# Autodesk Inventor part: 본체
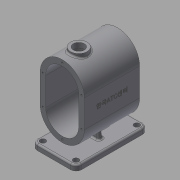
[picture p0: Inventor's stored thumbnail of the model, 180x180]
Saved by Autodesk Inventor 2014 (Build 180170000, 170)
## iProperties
Created: 2016-12
Part Number: 본체
Material: 일반
Document SubType Name: Modeling
Designer: mduedu
Density: 1 g/cm^3
Appearance: Default
Author: mduedu
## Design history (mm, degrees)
sketch "스케치1"
  geometry: L1 (40, -25)-(40, 25); L2 (-40, 25)-(-40, -25); L3 (-40, -25)-(40, 25); L4 (40, -25)-(-40, 25); L5 (0, 25)-(0, -25); A1 r 40 centre (0, 25) between (40, 25) and (-40, 25); A2 r 40 centre (0, -25) between (-40, -25) and (40, -25); 1 further point
  constraints: 10 end point, 4 point on circle, 3 tangent, 2 centre point, 2 midpoint, 2 parallel, 1 vertical
  dimensions: "d0" = 130 dimension on A2 A1; "d2" = 80 distance between parallel lines of L1 L2
extrude "돌출1" new body sketch "스케치1" stored distance "d3" = 100; taper "d4" = 0 deg
feature "쉘1" dims "d5" = 10
sketch "스케치2"
  geometry: L1 (-75, 65)-(-85, 65); L2 (-85, 65)-(-85, -65); L3 (-85, -65)-(-75, -65); L4 (-75, -65)-(-75, 65); 2 further points
  constraints: 8 end point, 2 parallel, 1 horizontal, 1 horizontal alignment, 1 midpoint, 1 perpendicular
  dimensions: "d6" = 85 distance from line of L2 point (0, 0); "d7" = 130 distance of L1.end L2.end; "d8" = 10 distance of L2.end L3.end
extrude "돌출2" join sketch "스케치2" stored distance "d9" = 80; taper "d10" = 0 deg
fillet "모깎기1" dims "d11" = 10
sketch "스케치3"
  geometry: L1 (-10, 10)-(-10, 120) reference; L2 (60, 0)-(0, 0) reference; L3 (70, 120)-(70, 10) reference; L4 (0, 130)-(60, 130) reference; A1 r 10 centre (0, 120) between (0, 130) and (-10, 120) reference; A2 r 10 centre (0, 10) between (-10, 10) and (0, 0) reference; A3 r 10 centre (60, 10) between (60, 0) and (70, 10) reference; A4 r 10 centre (60, 120) between (70, 120) and (60, 130) reference; 5 further points
  constraints: 4 coincident
hole "구멍1" sketch "스케치3" at (60, 120), (60, 10), (0, 10), (0, 120) diameter "d12" = 10; stored, may be unused: countersink angle "d16" = 90 deg, drill point angle "d18" = 118 deg; dims "d13" = 6, "d14" = 4, "d15" = 2, "d17" = 8
sketch "스케치5"
  geometry: L1 (34, 35)-(26, 35); L2 (26, 35)-(26, 95); L3 (26, 95)-(34, 95); L4 (34, 95)-(34, 35); L5 (34, 35)-(26, 95); L6 (26, 35)-(34, 95); 1 further point
  constraints: 12 end point, 2 midpoint, 2 parallel, 1 horizontal, 1 perpendicular
  dimensions: "d22" = 8 distance of L2.end L3.end; "d24" = 60 distance of L1.end L2.end
extrude "돌출3" join sketch "스케치5" stored distance "d25" = 80; taper "d26" = 0 deg
feature "면 기울기1" dims angle "d27" = 5 deg
sketch "스케치6"
  geometry: L1 (-30, -75)-(30, -75) reference; L2 (-17.524, -60.957)-(-20, -75); A1 r 40 centre (0, -25) between (-40, -25) and (40, -25) reference; 1 further point
  constraints: 2 end point, 1 point on circle, 1 point on line
  dimensions: "d28" = 20 horizontal distance of A1.centre L2.end; "d29" = 80 deg angle of L2 L1
feature "리브1" sketch "스케치6" dims "d30" = 1, "d31" = 8, "d32" = 0, "d33" = 0, "d34" = 1, "d35" = 1
fillet "모깎기2" dims "d36" = 3
fillet "모깎기3" dims "d37" = 3, "d38" = 3
node "작업 평면1"
sketch "스케치9"
  geometry: 1 further point
sketch "스케치7"
  geometry: L1 (40, 50)-(-40, 50) reference; C1 r 15 at (0, 20); 1 further point
  constraints: 1 centre point, 1 vertical alignment
  dimensions: "d40" = 30 diameter of C1; "d41" = 30 distance from line of C1.centre L1
extrude "돌출4" join sketch "스케치7" stored distance "d42" = 80; taper "d43" = 0 deg
hole "구멍2" diameter "d46" = 20; stored, may be unused: countersink angle "d50" = 90 deg, drill point angle "d52" = 118 deg; dims "d44" = 10, "d45" = 10, "d47" = 6, "d48" = 4, "d49" = 2, "d51" = 8
fillet "모깎기4" dims "d53" = 3
node "작업 평면2"
sketch "스케치8"
  geometry: C1 r 15 at (0, 0) reference; C2 r 15 at (0, 0); 1 further point
  constraints: 1 centre point, 1 coincident
  dimensions: "d55" = 30 diameter of C2
extrude "돌출5" cut sketch "스케치8" stored distance "d56" = 80; taper "d57" = 0 deg
chamfer "모따기1" distance "d58" = 1; stored, may be unused: second distance "d59" = 2, angle "d60" = 45 deg
sketch "스케치10"
  geometry: 2 further points
  constraints: 1 coincident, 1 other
feature "엠보싱1" sketch "스케치10" dims "d0" = 130, "d2" = 80, "d61" = 0.5, "d62" = 0
sketch "스케치11"
  geometry: 1 further point
hole "구멍3" sketch "스케치11" at (0, 60) diameter "d63" = 3.242; stored, may be unused: countersink angle "d67" = 90 deg, drill point angle "d69" = 120 deg; dims "d64" = 8.6, "d65" = 4, "d66" = 2, "d68" = 10.6
sketch "스케치12"
  geometry: 1 further point
hole "구멍5" sketch "스케치12" at (0, 60) diameter "d70" = 3.242; stored, may be unused: countersink angle "d74" = 90 deg, drill point angle "d76" = 120 deg; dims "d71" = 8.6, "d72" = 4, "d73" = 2, "d75" = 10.6
node "솔리드1"
mirror "대칭1"
pattern_linear "직사각형 패턴1"
pattern_linear "직사각형 패턴2"
node "투영된 루프1"
sketch "스케치13"
  geometry: L1 (-40, 25)-(-40, -25) reference; L2 (40, -25)-(40, 25) reference; L3 (35, 25)-(35, -25); L4 (-35, -25)-(-35, 25); A1 r 40 centre (0, 25) between (40, 25) and (-40, 25) reference; A2 r 40 centre (0, -25) between (-40, -25) and (40, -25) reference; A3 r 35 centre (0, 25) between (35, 25) and (-35, 25); A4 r 35 centre (0, -25) between (-35, -25) and (35, -25); 2 further points
  constraints: 5 point on circle, 4 end point, 2 centre point, 3 other
  dimensions: "d77" = 5 distance between parallel lines of L3 L2
sketch "스케치14"
  geometry: L1 (-40, 25)-(-40, -25) reference; L2 (40, -25)-(40, 25) reference; L3 (35, 25)-(35, -25); L4 (-35, -25)-(-35, 25); A1 r 40 centre (0, 25) between (40, 25) and (-40, 25) reference; A2 r 40 centre (0, -25) between (-40, -25) and (40, -25) reference; A3 r 35 centre (0, 25) between (35, 25) and (-35, 25); A4 r 35 centre (0, -25) between (-35, -25) and (35, -25); 2 further points
  constraints: 5 point on circle, 4 end point, 2 centre point, 3 other
  dimensions: "d80" = 5 distance between parallel lines of L2 L3
